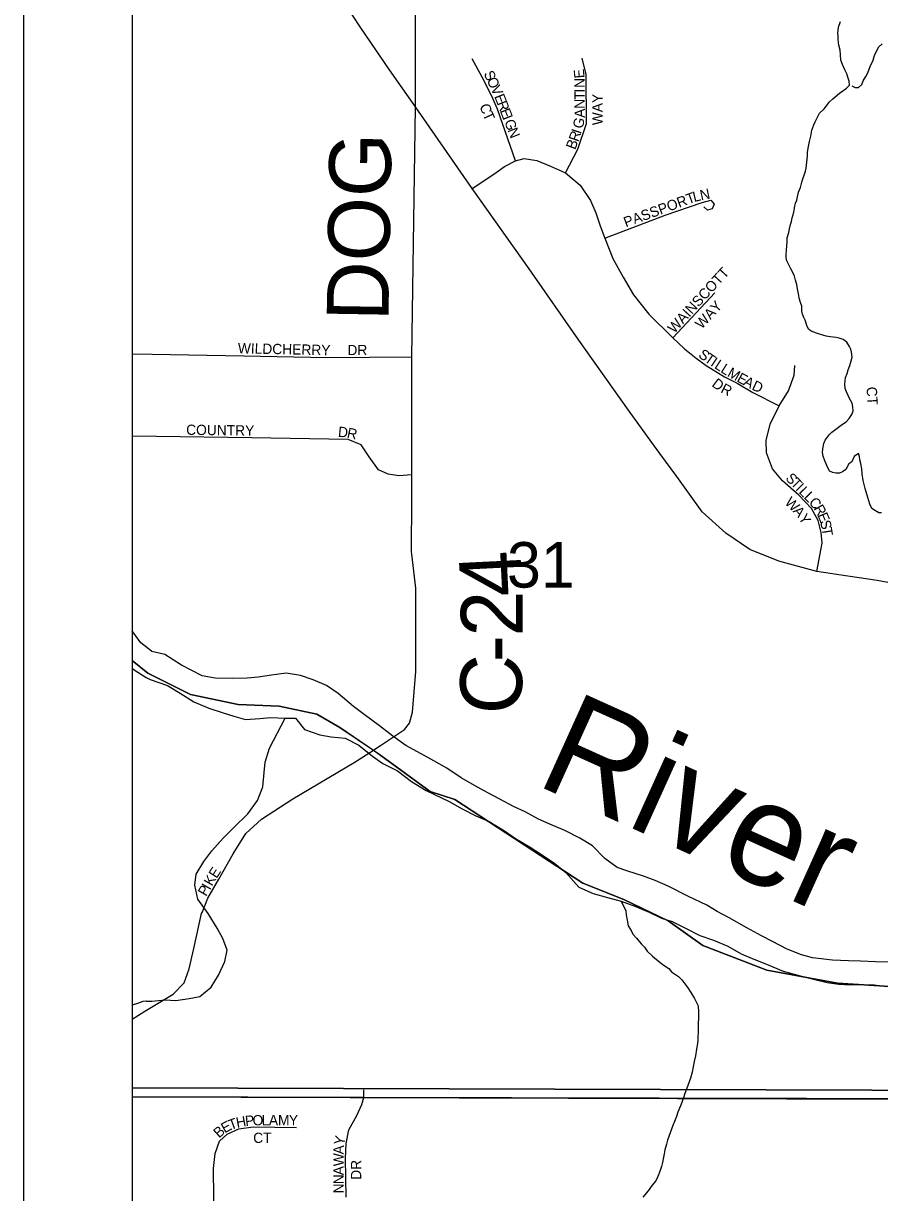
# Model space of a CAD drawing. Extents: x 8.5 to 81.5, y -1.2 to 22.4.
# Drawn here: x 49.353 to 50.14, y 15.672 to 16.747 of the extents above; entities that cross this region are included whole.
import ezdxf

# ---------------------------------------------------------------- set-up
doc = ezdxf.new("R2010")
doc.units = 0
for name, color, linetype in [('GM_X_City_Street', 7, 'Continuous'), ('GM_X_City_Street_Text', 7, 'Continuous'), ('GM_X_Corporation', 7, 'Continuous'), ('GM_X_County', 7, 'Continuous'), ('GM_X_County_Road', 7, 'Continuous'), ('GM_X_County_Road_Text', 7, 'Continuous'), ('GM_X_Major_River', 7, 'Continuous'), ('GM_X_Major_River_Text', 7, 'Continuous'), ('GM_X_Minor_River', 7, 'Continuous'), ('GM_X_Section', 7, 'Continuous'), ('GM_X_Section_Text', 7, 'Continuous'), ('GM_X_Township', 7, 'Continuous'), ('GM_X_Township_Subdivision', 7, 'Continuous'), ('GM_X_Township_Subdivision_Text', 7, 'Continuous'), ('SH_Data', 7, 'Continuous')]:
    doc.layers.add(name, color=color, linetype=linetype)

msp = doc.modelspace()

# ---------------------------------------------------------------- linework, layer by layer
at = {"layer": 'GM_X_City_Street'}
for points in [[(49.7098, 16.3094), (49.7099, 16.3295)], [(49.517, 15.9296), (49.5173, 15.9304), (49.5223, 15.943), (49.5325, 15.9604), (49.5455, 15.9835), (49.5571, 16.0024), (49.5715, 16.0154), (49.6005, 16.0342), (49.6569, 16.0675), (49.6745, 16.079), (49.6805, 16.0829)], [(49.4527, 15.8316), (49.4645, 15.8388), (49.4905, 15.8547), (49.5006, 15.8649), (49.505, 15.8779), (49.5093, 15.8967), (49.5166, 15.9286), (49.517, 15.9296)]]:
    msp.add_lwpolyline(points, dxfattribs=at)
at = {"layer": 'GM_X_Corporation'}
msp.add_line((49.4527, 16.1615), (49.4527, 15.7601), dxfattribs=at)
for points in [[(50.1492, 15.8615), (50.101, 15.8646), (50.0361, 15.8766), (49.9772, 15.8993), (49.9455, 15.9219), (49.9048, 15.9415), (49.867, 15.9566), (49.7493, 16.0335), (49.7267, 16.0411), (49.6814, 16.0742), (49.6437, 16.0999), (49.6226, 16.112), (49.5878, 16.1195), (49.5501, 16.121), (49.5064, 16.1301), (49.4671, 16.1497), (49.4527, 16.1615)], [(49.4527, 15.7601), (50.7559, 15.7562)]]:
    msp.add_lwpolyline(points, dxfattribs=at)
at = {"layer": 'GM_X_County'}
msp.add_lwpolyline([(54.0879, 21.2506), (49.4527, 21.2506), (49.4527, 14.4506), (56.2527, 14.4506), (56.2527, 19.1108)], dxfattribs=at)
at = {"layer": 'GM_X_County_Road'}
for points in [[(49.7133, 16.6708), (49.6892, 16.7047), (49.663, 16.7434), (49.6475, 16.7668), (49.6388, 16.7814), (49.6035, 16.8415), (49.569, 16.9023), (49.5302, 16.9672), (49.4912, 17.0405), (49.4536, 17.1067), (49.4527, 17.1086)], [(49.7099, 16.3295), (49.7099, 16.3321), (49.7099, 16.3621), (49.7098, 16.4403), (49.7119, 16.5869), (49.7133, 16.6708), (49.7133, 16.7659)], [(49.9304, 16.3621), (49.9089, 16.3917), (49.8633, 16.4562), (49.8177, 16.5218), (49.7654, 16.5956), (49.7133, 16.6708)], [(50.3246, 16.2088), (50.2366, 16.2198), (50.1963, 16.2257), (50.1637, 16.2302), (50.1377, 16.2351), (50.1106, 16.2391), (50.0822, 16.2433), (50.0473, 16.2529), (50.0206, 16.2634), (49.9985, 16.2787), (49.9767, 16.2983), (49.9534, 16.3306), (49.9379, 16.3518), (49.9304, 16.3621)], [(49.7097, 16.2592), (49.7094, 16.2617), (49.7098, 16.3094)], [(49.6805, 16.0829), (49.6809, 16.0832), (49.7032, 16.0979), (49.7076, 16.1037), (49.7105, 16.1138), (49.7134, 16.1514), (49.7134, 16.2281), (49.7097, 16.2592)]]:
    msp.add_lwpolyline(points, dxfattribs=at)
at = {"layer": 'GM_X_Major_River'}
for points in [[(49.4709, 16.1697), (49.4705, 16.1701), (49.4608, 16.1778), (49.4533, 16.1878), (49.4527, 16.1887)], [(50.161, 15.8838), (50.136, 15.8843), (50.1223, 15.885), (50.1113, 15.8852), (50.0965, 15.8859), (50.0783, 15.8881), (50.0681, 15.8906), (50.0549, 15.8958), (50.0414, 15.9029), (50.0312, 15.9081), (50.0177, 15.9156), (50.0015, 15.9247), (49.9906, 15.9306), (49.9809, 15.9365), (49.9643, 15.9444), (49.9455, 15.9539), (49.9334, 15.9591), (49.9229, 15.9631), (49.9085, 15.9676), (49.8987, 15.9712), (49.8871, 15.9794), (49.8759, 15.991), (49.8643, 15.9981), (49.8504, 16.0052), (49.8368, 16.0108), (49.8263, 16.0156), (49.8139, 16.0223), (49.8033, 16.0271), (49.7906, 16.0338), (49.7797, 16.0397), (49.7673, 16.0464), (49.7552, 16.0535), (49.7421, 16.0625), (49.7301, 16.0692), (49.7184, 16.0755), (49.7042, 16.0834), (49.6922, 16.092), (49.6802, 16.1014), (49.666, 16.1119), (49.6562, 16.119), (49.642, 16.1311), (49.6315, 16.1385), (49.6191, 16.1437), (49.6074, 16.1477), (49.5942, 16.1499), (49.5808, 16.1479), (49.5686, 16.1462), (49.5584, 16.1453), (49.5447, 16.1448), (49.5291, 16.1451), (49.517, 16.1473), (49.4982, 16.1571), (49.4827, 16.1669), (49.4709, 16.1697)], [(49.4527, 16.1545), (49.4547, 16.1528), (49.4655, 16.1458), (49.4693, 16.1439)], [(49.4693, 16.1439), (49.4853, 16.1384), (49.4969, 16.1313), (49.5093, 16.1235), (49.5233, 16.1175), (49.5365, 16.1134), (49.5463, 16.1102), (49.5569, 16.1073), (49.5702, 16.1082), (49.5801, 16.1091), (49.5934, 16.1085), (49.6028, 16.1083), (49.611, 16.0979), (49.6253, 16.093), (49.6356, 16.0913), (49.6484, 16.0899), (49.6612, 16.0835), (49.6736, 16.0734), (49.6833, 16.0668), (49.6965, 16.06), (49.7096, 16.0503), (49.7231, 16.042), (49.7442, 16.0317), (49.7562, 16.025), (49.7686, 16.0187), (49.781, 16.0135), (49.7949, 16.0048), (49.805, 15.9978), (49.8186, 15.9899), (49.8291, 15.9829), (49.8414, 15.9746), (49.8515, 15.9665), (49.8634, 15.9529), (49.8766, 15.947), (49.8898, 15.9436), (49.9023, 15.94), (49.9147, 15.9355), (49.9279, 15.93), (49.9392, 15.9244), (49.949, 15.9215), (49.9614, 15.9152), (49.9746, 15.9085), (49.9871, 15.9041), (50.0002, 15.8988), (50.0126, 15.8918), (50.0228, 15.8874), (50.036, 15.8822), (50.0511, 15.8758), (50.0647, 15.8721), (50.0779, 15.8688), (50.0915, 15.8654), (50.1025, 15.8637), (50.1124, 15.8631), (50.1249, 15.8633), (50.1348, 15.8631), (50.1461, 15.8617)]]:
    msp.add_lwpolyline(points, dxfattribs=at)
at = {"layer": 'GM_X_Minor_River'}
for points in [[(50.0718, 16.6116), (50.0723, 16.6142), (50.0728, 16.6199), (50.0736, 16.6252), (50.0737, 16.629), (50.0746, 16.6343), (50.0754, 16.6388), (50.0767, 16.6438), (50.0775, 16.6491), (50.0795, 16.654), (50.0807, 16.657), (50.0827, 16.6611), (50.0847, 16.6649), (50.089, 16.669), (50.0913, 16.672), (50.0936, 16.675), (50.0967, 16.678), (50.1029, 16.6832), (50.106, 16.6854), (50.1095, 16.688), (50.1122, 16.6906), (50.1119, 16.6944), (50.1108, 16.6971), (50.1097, 16.7009), (50.1079, 16.7047), (50.1057, 16.7097), (50.1043, 16.7135), (50.104, 16.7185), (50.1037, 16.7227), (50.1023, 16.7273), (50.102, 16.7299), (50.1017, 16.733), (50.1017, 16.7356), (50.1014, 16.7383), (50.1019, 16.744), (50.1039, 16.7493)], [(50.1144, 16.6901), (50.1174, 16.6886), (50.1205, 16.6885), (50.1236, 16.6911), (50.1248, 16.6945), (50.1271, 16.6986), (50.1291, 16.702), (50.1311, 16.7077), (50.1339, 16.7137), (50.1351, 16.7179), (50.1371, 16.722), (50.1391, 16.7258), (50.1422, 16.7287)], [(50.1308, 16.3052), (50.129, 16.3113), (50.1266, 16.3197), (50.1248, 16.327), (50.1238, 16.3331), (50.1235, 16.3376), (50.1225, 16.3426), (50.1218, 16.346), (50.1215, 16.3491), (50.1204, 16.3518), (50.1165, 16.3492), (50.1142, 16.3443), (50.1115, 16.3424), (50.1087, 16.3372), (50.1056, 16.335), (50.1029, 16.3339), (50.0995, 16.3339), (50.0969, 16.3344), (50.0939, 16.3356), (50.0913, 16.3409), (50.0895, 16.3452), (50.0881, 16.3494), (50.0874, 16.3528), (50.0875, 16.3562), (50.0887, 16.3611), (50.0899, 16.3642), (50.0934, 16.369), (50.0958, 16.3716), (50.1019, 16.3761), (50.1058, 16.3787), (50.1092, 16.3809), (50.1119, 16.3839), (50.1143, 16.3876), (50.1155, 16.391), (50.1152, 16.3948), (50.1145, 16.3982), (50.1123, 16.4025), (50.1109, 16.4052), (50.1094, 16.4086), (50.1083, 16.4117), (50.108, 16.4155), (50.1085, 16.4216), (50.1101, 16.4253), (50.111, 16.4287), (50.1126, 16.4329), (50.1138, 16.437), (50.1146, 16.4404), (50.114, 16.445), (50.1133, 16.4477), (50.1122, 16.4504), (50.1096, 16.4542), (50.1062, 16.4566), (50.1028, 16.4578), (50.0998, 16.4586), (50.0945, 16.4591), (50.0907, 16.4599), (50.0877, 16.4607), (50.0836, 16.462), (50.0775, 16.464), (50.0749, 16.4659), (50.0731, 16.4686), (50.0713, 16.4744), (50.0702, 16.477), (50.0691, 16.4801), (50.0684, 16.4832), (50.0682, 16.4873), (50.0671, 16.4908), (50.066, 16.4946), (50.0657, 16.4973), (50.065, 16.5003), (50.0643, 16.5034), (50.0636, 16.5072), (50.0626, 16.5114), (50.0615, 16.5148), (50.0601, 16.5183), (50.0582, 16.5218), (50.056, 16.526), (50.0546, 16.529), (50.0539, 16.5321), (50.0539, 16.5348), (50.0544, 16.5386), (50.0545, 16.5431), (50.0549, 16.5465), (50.055, 16.5503), (50.0563, 16.5552), (50.0571, 16.5586), (50.0579, 16.5624), (50.0587, 16.5651), (50.0596, 16.5685), (50.0604, 16.5715), (50.0612, 16.5753), (50.0617, 16.5779), (50.0625, 16.5821), (50.0637, 16.5847), (50.0646, 16.5893), (50.0654, 16.5923), (50.067, 16.5964), (50.0682, 16.6014), (50.0694, 16.6044), (50.0706, 16.6078), (50.0718, 16.6116)], [(50.1417, 16.2974), (50.139, 16.2974), (50.136, 16.299), (50.1326, 16.3013), (50.1308, 16.3052)], [(49.4656, 15.848), (49.4708, 15.848), (49.483, 15.8493), (49.4929, 15.8487), (49.5051, 15.8507), (49.515, 15.8524), (49.5254, 15.861), (49.5321, 15.8719), (49.538, 15.8847), (49.5401, 15.8949), (49.5362, 15.9056), (49.531, 15.9152), (49.5226, 15.9287), (49.513, 15.9418), (49.5102, 15.9548), (49.5115, 15.965), (49.5186, 15.9766), (49.526, 15.9864), (49.5365, 15.9979), (49.5458, 16.0076), (49.5589, 16.0203), (49.5679, 16.0326), (49.5727, 16.0454), (49.5741, 16.0583), (49.5751, 16.0678), (49.5791, 16.0807), (49.5934, 16.1085)], [(49.9023, 15.94), (49.9065, 15.9311), (49.9068, 15.9276), (49.9078, 15.9227), (49.9088, 15.9173), (49.9114, 15.9131), (49.9129, 15.9096), (49.9162, 15.9062), (49.9206, 15.9008), (49.9236, 15.8977), (49.9262, 15.8942), (49.931, 15.8895), (49.9381, 15.8837), (49.9419, 15.8809), (49.946, 15.8782), (49.9486, 15.8751), (49.9549, 15.8708), (49.9579, 15.8677), (49.9609, 15.8642), (49.9634, 15.8604), (49.9664, 15.8561), (49.9697, 15.8507), (49.973, 15.8438), (49.9732, 15.8381), (49.9729, 15.8225), (49.9727, 15.8119), (49.9722, 15.8073), (49.9714, 15.8039), (49.9705, 15.7979), (49.9693, 15.7926), (49.9675, 15.7827), (49.9659, 15.7774), (49.9623, 15.7672), (49.9607, 15.7631), (49.9595, 15.7593), (49.9583, 15.7559), (49.9567, 15.7518), (49.9543, 15.7461), (49.953, 15.742), (49.9514, 15.7374), (49.9498, 15.7337), (49.9462, 15.7235), (49.945, 15.7204), (49.9438, 15.7167), (49.9425, 15.7114), (49.9417, 15.7076), (49.9409, 15.703), (49.9404, 15.6996), (49.9392, 15.6959), (49.938, 15.6925), (49.936, 15.6868), (49.934, 15.683), (49.9309, 15.6789), (49.927, 15.6737), (49.9223, 15.6677)], [(49.4656, 15.848), (49.4626, 15.8477), (49.4576, 15.8459), (49.4527, 15.8444)]]:
    msp.add_lwpolyline(points, dxfattribs=at)
at = {"layer": 'GM_X_Section'}
for p, q in [((49.4527, 16.7724), (49.4527, 15.7683)), ((49.4527, 15.7683), (49.4527, 14.8223))]:
    msp.add_line(p, q, dxfattribs=at)
for points in [[(49.4527, 15.7683), (50.2298, 15.7659), (50.2406, 16.7675), (49.4527, 16.7724)], [(49.4527, 14.8223), (50.2203, 14.8143), (50.2298, 15.7659), (49.4527, 15.7683)]]:
    msp.add_lwpolyline(points, dxfattribs=at)
at = {"layer": 'GM_X_Township'}
for points in [[(54.0879, 21.2506), (49.4527, 21.2506), (49.4527, 16.1615)], [(49.4527, 16.1615), (49.4671, 16.1497), (49.5064, 16.1301), (49.5501, 16.121), (49.5878, 16.1195), (49.6226, 16.112), (49.6437, 16.0999), (49.6745, 16.079), (49.6814, 16.0742), (49.7267, 16.0411), (49.7493, 16.0335), (49.867, 15.9566), (49.9048, 15.9415), (49.9455, 15.9219), (49.9772, 15.8993), (50.0361, 15.8766), (50.101, 15.8646), (50.1492, 15.8615)], [(49.4527, 15.7601), (49.4527, 14.4506), (54.4602, 14.4506)], [(51.5756, 15.7537), (51.1938, 15.7549), (50.803, 15.7561), (50.7559, 15.7562), (50.5195, 15.7577), (50.4799, 15.7578), (49.6657, 15.7594), (49.4527, 15.7601)]]:
    msp.add_lwpolyline(points, dxfattribs=at)
at = {"layer": 'GM_X_Township_Subdivision'}
for points in [[(49.8052, 16.6209), (49.7885, 16.6686), (49.783, 16.6811), (49.7745, 16.698), (49.7654, 16.7147)], [(49.8512, 16.6099), (49.8624, 16.6317), (49.8704, 16.6554), (49.8702, 16.7005), (49.8664, 16.7154)], [(49.7654, 16.5956), (49.777, 16.6031), (49.7872, 16.6103), (49.795, 16.6158), (49.8052, 16.6209), (49.8132, 16.6232), (49.8247, 16.6213), (49.8374, 16.616), (49.8512, 16.6099), (49.8647, 16.5987), (49.8742, 16.5845), (49.8789, 16.5731), (49.8829, 16.5612), (49.8872, 16.5498), (49.8946, 16.5313), (49.9041, 16.514), (49.9136, 16.4977), (49.9278, 16.4801), (49.9496, 16.4581), (49.9604, 16.4481), (49.9712, 16.4394), (49.9805, 16.4327), (49.9971, 16.4223), (50.0089, 16.4166), (50.0232, 16.4079), (50.0475, 16.3956)], [(49.8872, 16.5498), (49.9426, 16.5709), (49.9767, 16.5828), (49.9848, 16.5849), (49.9877, 16.5811), (49.9858, 16.5769), (49.9816, 16.5758), (49.9784, 16.5786)], [(49.9496, 16.4581), (49.9885, 16.4997)], [(49.7098, 16.4403), (49.632, 16.4399), (49.5553, 16.4414), (49.4712, 16.4428), (49.4527, 16.4432)], [(50.0822, 16.2433), (50.0869, 16.2694), (50.086, 16.2791), (50.0835, 16.2901), (50.0771, 16.3013), (50.0655, 16.3134), (50.0506, 16.3268), (50.0413, 16.3378), (50.036, 16.3526), (50.0356, 16.3638), (50.0392, 16.3789), (50.0475, 16.3956), (50.0562, 16.4096), (50.0612, 16.4238), (50.0619, 16.4329)], [(49.7099, 16.3321), (49.6979, 16.3314), (49.6881, 16.3328), (49.6792, 16.3367), (49.6705, 16.3487), (49.6633, 16.3597), (49.6512, 16.3647), (49.5625, 16.3662), (49.4751, 16.3675), (49.4527, 16.3678)], [(49.6493, 15.6677), (49.6487, 15.7034), (49.6493, 15.7173), (49.652, 15.7299), (49.6593, 15.7431), (49.6639, 15.7531), (49.6657, 15.7594), (49.6657, 15.7666)], [(49.5329, 15.7193), (49.5402, 15.7259), (49.5507, 15.7306), (49.564, 15.7325), (49.6037, 15.7319)], [(49.5458, 15.5704), (49.5355, 15.581), (49.5309, 15.5909), (49.5282, 15.6062), (49.5282, 15.6412), (49.5276, 15.6942), (49.5289, 15.7081), (49.5329, 15.7193)]]:
    msp.add_lwpolyline(points, dxfattribs=at)
at = {"layer": 'SH_Data'}
for p, q in [((49.3527, 21.3506), (49.3527, 14.3506)), ((49.4527, 21.2506), (49.4527, 14.4506))]:
    msp.add_line(p, q, dxfattribs=at)

# ---------------------------------------------------------------- texts
at = {"layer": 'GM_X_City_Street_Text'}
for s, rotation, p in [('E', 57.4995, (49.5303, 15.9604)), ('K', 60.0409, (49.5261, 15.9533)), ('P', 60.0484, (49.5207, 15.9439)), ('I', 60.0464, (49.5241, 15.9497))]:
    msp.add_text(s, height=0.00947, rotation=rotation, dxfattribs=at).set_placement(p)
at = {"layer": 'GM_X_County_Road_Text'}
for s, height, rotation, p in [('DOG', 0.05682, 89.0543, (49.6883, 16.4733)), ('4', 0.0568, 92.8365, (49.8116, 16.2213)), ('2', 0.0568, 90.2141, (49.8118, 16.1835)), ('-', 0.0568, 89.7526, (49.8117, 16.1596)), ('C', 0.0568, 87.9934, (49.8101, 16.1111))]:
    msp.add_text(s, height=height, rotation=rotation, dxfattribs=at).set_placement(p)
at = {"layer": 'GM_X_Major_River_Text'}
msp.add_text('River', height=0.09469, rotation=335.6691, dxfattribs=at).set_placement((49.8218, 16.048))
at = {"layer": 'GM_X_Section_Text'}
msp.add_text('31', height=0.04186, rotation=0, dxfattribs=at).set_placement((49.7973, 16.2285))
at = {"layer": 'GM_X_Township_Subdivision_Text'}
for s, rotation, p in [('S', 295.5021, (49.7756, 16.7013)), ('E', 95.0571, (49.8687, 16.6973)), ('O', 295.4823, (49.7784, 16.6953)), ('V', 294.3553, (49.782, 16.6878)), ('N', 90.207, (49.8688, 16.6881)), ('E', 291.8674, (49.7854, 16.6803)), ('I', 90.1748, (49.8688, 16.6839)), ('T', 90.2087, (49.8688, 16.6772)), ('WAY', 90, (49.8851, 16.6538)), ('C', 289.4872, (49.7719, 16.6717)), ('R', 291.4001, (49.7879, 16.6741)), ('E', 291.4153, (49.7906, 16.6671)), ('N', 90.1968, (49.8688, 16.6689)), ('T', 294.447, (49.7747, 16.6638)), ('I', 291.4361, (49.793, 16.6609)), ('G', 291.4078, (49.7946, 16.6571)), ('G', 77.1584, (49.8668, 16.6501)), ('A', 90.2745, (49.8689, 16.6606)), ('N', 291.4158, (49.7976, 16.6493)), ('R', 71.1322, (49.8627, 16.638)), ('I', 71.3206, (49.8651, 16.6451)), ('B', 69.4837, (49.86, 16.6307)), ('N', 11.7986, (49.9757, 16.5846)), ('PASSPORT', 20.2617, (49.9066, 16.5597)), ('L', 13.5127, (49.9693, 16.5831)), ('WAINSCOTT', 47.4882, (49.951, 16.4617)), ('WAY', 47.3844, (49.9763, 16.4657)), ('WILDCHERRY', 358.7664, (49.5498, 16.444)), ('DR', 0, (49.6506, 16.4423)), ('S', 324.059, (49.9725, 16.4411)), ('T', 325.2028, (49.9781, 16.4371)), ('I', 326.6227, (49.9838, 16.4331)), ('L', 327.0206, (49.9873, 16.4308)), ('L', 328.0394, (49.993, 16.4271)), ('M', 330.8137, (49.9991, 16.4233)), ('E', 331.349, (50.0079, 16.4184)), ('A', 331.4107, (50.0138, 16.4152)), ('D', 322.9684, (49.9849, 16.4143)), ('R', 332.8112, (49.993, 16.4084)), ('D', 335.2649, (50.0217, 16.4109)), ('CT', 273.1778, (50.1278, 16.413)), ('COUNTRY', 359.2528, (49.5023, 16.369)), ('D', 354.0436, (49.6416, 16.3673)), ('R', 348.1851, (49.6496, 16.3665)), ('S', 314.4978, (50.0527, 16.3284)), ('T', 314.4978, (50.0574, 16.3237)), ('I', 314.5056, (50.062, 16.3189)), ('L', 314.4978, (50.065, 16.316)), ('L', 314.4978, (50.0696, 16.3112)), ('W', 314.8336, (50.052, 16.3061)), ('C', 311.8554, (50.0742, 16.3065)), ('R', 300.0642, (50.0789, 16.3014)), ('A', 311.2106, (50.0596, 16.2985)), ('Y', 302.1259, (50.0648, 16.2926)), ('E', 292.4203, (50.0825, 16.2952)), ('S', 283.4267, (50.085, 16.2894)), ('T', 279.1076, (50.0865, 16.2831)), ('B', 42.1136, (49.5326, 15.7217)), ('E', 28.9113, (49.5377, 15.7264)), ('T', 19.9901, (49.5432, 15.7294)), ('H', 10.5512, (49.5491, 15.7316)), ('P', 5.7459, (49.557, 15.7331)), ('O', 1.2895, (49.5635, 15.7338)), ('L', 0.082, (49.5718, 15.7339)), ('A', 0, (49.5784, 15.734)), ('M', 0, (49.5868, 15.734)), ('Y', 0, (49.5968, 15.734)), ('CT', 0, (49.564, 15.7177)), ('Y', 78.7801, (49.6473, 15.715)), ('A', 89.1912, (49.6472, 15.7071)), ('W', 89.9327, (49.6472, 15.6963)), ('DR', 90, (49.6633, 15.6838)), ('A', 89.9344, (49.6472, 15.688)), ('N', 89.9344, (49.6472, 15.6797)), ('N', 89.9344, (49.6472, 15.6713))]:
    msp.add_text(s, height=0.00947, rotation=rotation, dxfattribs=at).set_placement(p)

doc.saveas('drawing.dxf')
